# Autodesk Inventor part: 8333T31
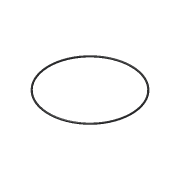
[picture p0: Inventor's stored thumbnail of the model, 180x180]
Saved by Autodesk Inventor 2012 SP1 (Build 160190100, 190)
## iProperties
Created: 2012-03
Part Number: 8333T31
Material: Silicone
Document SubType Name: Modeling
Designer: jdh
Density: 1.25 g/cm^3
Mass: 6.71161 g
Surface Area: 60.8315 cm^2
Volume: 5.36929 cm^3
Author: jdh
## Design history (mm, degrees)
sketch "Sketch1"
  geometry: L1 (0, 0)-(-93.637, 0); L2 (-95.402, 3.721)-(-95.402, -3.403); L3 (-91.872, 2.64)-(-91.872, -3.976); L4 (0, -5.515)-(0, 5.261) reference; C1 r 1.765 at (-93.637, 0)
  constraints: 6 end point, 2 tangent, 1 centre point, 1 coincident, 1 horizontal, 1 parallel, 1 perpendicular
  dimensions: "d0" = 95.4024 distance from line of L1.start L2; "d1" = 91.8718 distance from line of L1.start L3
revolve "Revolution1" sketch "Sketch1" stored, may be unused: angle "d2" = 90 deg
body "Solid1"
